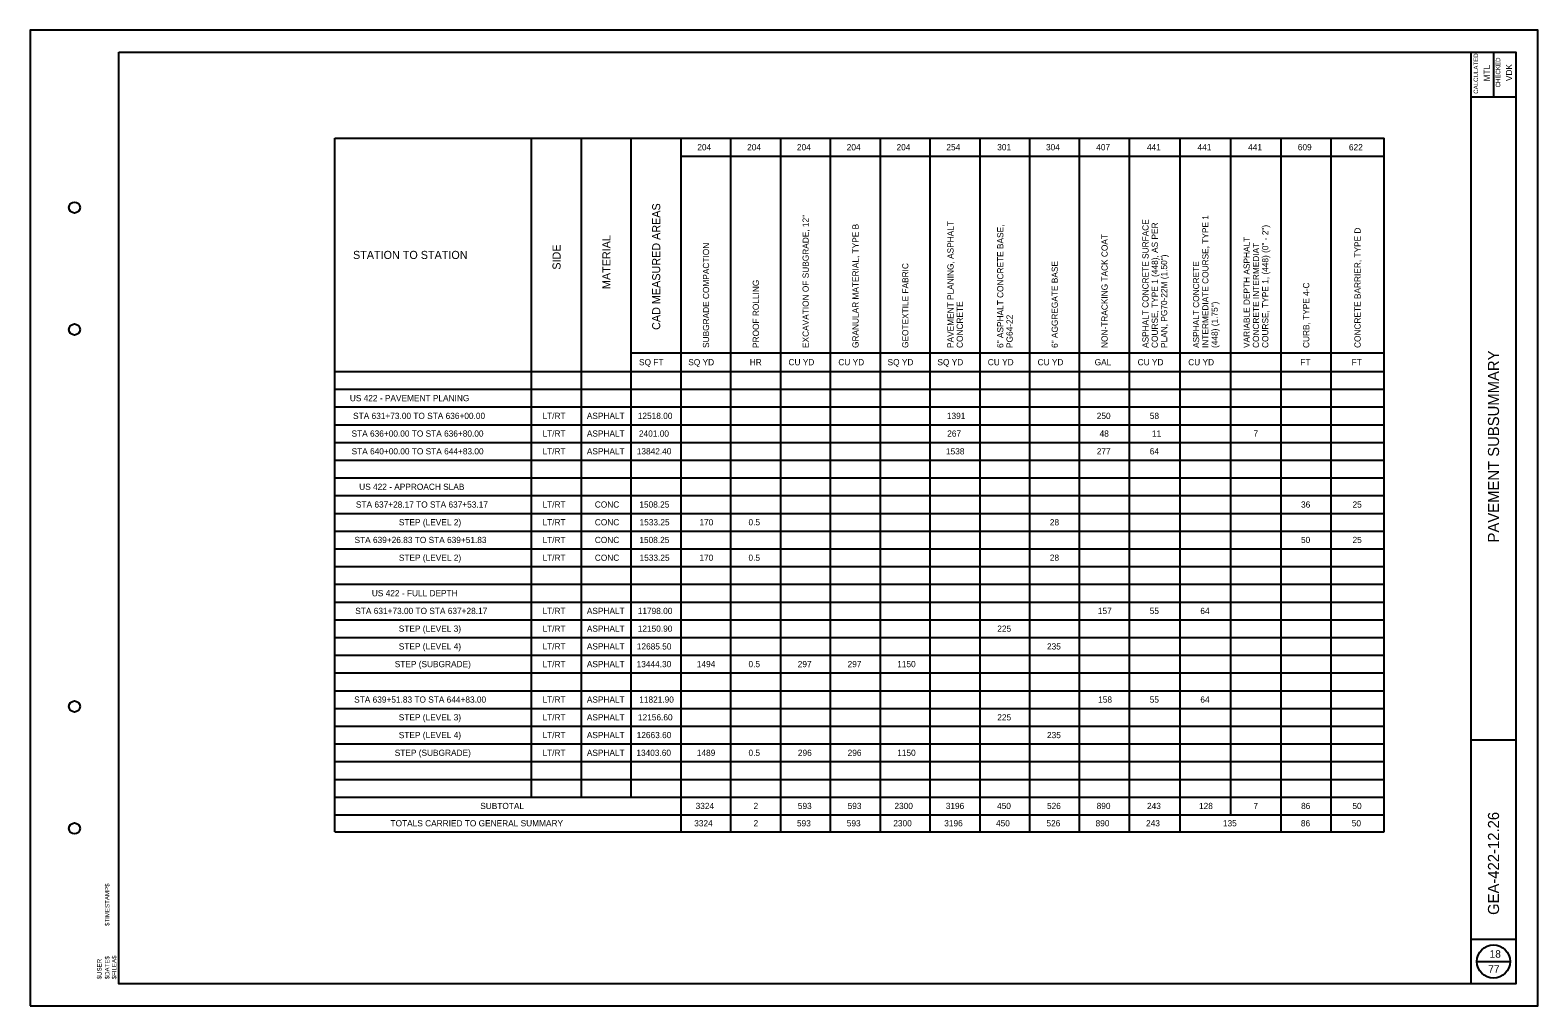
# Model space of a CAD drawing. Extents: x 0 to 34, y 0 to 22.
import ezdxf

# ---------------------------------------------------------------- set-up
doc = ezdxf.new("R2010")
doc.units = 0
for name, color, linetype in [('SH_Border', 7, 'Continuous'), ('SH_Cut_Line', 7, 'Continuous'), ('SH_Data', 7, 'Continuous'), ('SH_Text', 7, 'Continuous')]:
    doc.layers.add(name, color=color, linetype=linetype)

msp = doc.modelspace()

# ---------------------------------------------------------------- linework, layer by layer
at = {"layer": 'SH_Border'}
for p, q in [((32.5, 0.5), (32.5, 21.5)), ((33, 21.5), (33, 20.5)), ((32.5, 20.5), (33.5, 20.5)), ((32.5, 6), (33.5, 6)), ((32.5, 1.5), (33.5, 1.5))]:
    msp.add_line(p, q, dxfattribs=at)
msp.add_lwpolyline([(2, 21.5), (33.5, 21.5), (33.5, 0.5), (2, 0.5)], close=True, dxfattribs=at)
for centre in [(1, 18), (1, 15.25), (1, 6.75), (1, 4)]:
    msp.add_circle(centre, 0.125, dxfattribs=at)
at = {"layer": 'SH_Cut_Line'}
msp.add_lwpolyline([(0, 0), (34, 0), (34, 22), (0, 22)], close=True, dxfattribs=at)
at = {"layer": 'SH_Data'}
msp.add_line((32.625, 1), (33.375, 1), dxfattribs=at)
msp.add_circle((33, 1), 0.375, dxfattribs=at)
at = {"layer": 'SH_Text'}
for p, q in [((6.868, 19.561), (6.868, 19.561)), ((6.868, 19.561), (30.531, 19.561)), ((6.868, 3.927), (6.868, 19.561)), ((11.309, 4.707), (11.309, 19.561)), ((12.433, 4.707), (12.433, 19.561)), ((13.556, 4.707), (13.556, 19.561)), ((14.68, 3.927), (14.68, 19.561)), ((15.803, 3.927), (15.803, 19.561)), ((16.927, 3.927), (16.927, 19.561)), ((18.05, 3.927), (18.05, 19.561)), ((19.173, 3.927), (19.173, 19.561)), ((20.297, 3.927), (20.297, 19.561)), ((21.42, 3.927), (21.42, 19.561)), ((22.544, 3.927), (22.544, 19.561)), ((23.667, 3.927), (23.667, 19.561)), ((24.791, 3.927), (24.791, 19.561)), ((25.932, 3.927), (25.932, 19.561)), ((27.073, 4.307), (27.073, 19.561)), ((28.214, 3.927), (28.214, 19.561)), ((29.337, 3.927), (29.337, 19.561)), ((30.531, 3.927), (30.531, 19.561)), ((14.68, 19.161), (30.531, 19.161)), ((13.556, 14.723), (30.531, 14.723)), ((6.868, 14.303), (30.531, 14.303)), ((6.868, 13.903), (30.531, 13.903)), ((6.868, 13.503), (30.531, 13.503)), ((6.868, 13.103), (30.531, 13.103)), ((6.868, 12.704), (30.531, 12.704)), ((6.868, 12.304), (30.531, 12.304)), ((6.868, 11.904), (30.531, 11.904)), ((6.868, 11.504), (30.531, 11.504)), ((6.868, 11.104), (30.531, 11.104)), ((6.868, 10.704), (30.531, 10.704)), ((6.868, 10.305), (30.531, 10.305)), ((6.868, 9.905), (30.531, 9.905)), ((6.868, 9.505), (30.531, 9.505)), ((6.868, 9.105), (30.531, 9.105)), ((6.868, 8.705), (30.531, 8.705)), ((6.868, 8.305), (30.531, 8.305)), ((6.868, 7.906), (30.531, 7.906)), ((6.868, 7.506), (30.531, 7.506)), ((6.868, 7.106), (30.531, 7.106)), ((6.868, 6.706), (30.531, 6.706)), ((6.868, 6.306), (30.531, 6.306)), ((6.868, 5.906), (30.531, 5.906)), ((6.868, 5.507), (30.531, 5.507)), ((6.868, 5.107), (30.531, 5.107)), ((6.868, 4.707), (30.531, 4.707)), ((6.868, 4.307), (30.531, 4.307)), ((6.868, 3.927), (30.531, 3.927))]:
    msp.add_line(p, q, dxfattribs=at)

# ---------------------------------------------------------------- texts
at = {"layer": 'SH_Data'}
for s, height, rotation, p in [('CALCULATED', 0.1, 90, (32.652, 20.565)), ('MTL', 0.14, 90, (32.92, 20.844)), ('CHECKED', 0.1, 90, (33.152, 20.708)), ('VDK', 0.14, 90, (33.42, 20.851)), ('PAVEMENT SUBSUMMARY', 0.25, 90, (33.125, 10.449)), (' GEA-422-12.26 ', 0.25, 90, (33.125, 1.957)), ('$TIMESTAMP$', 0.1, 89.9931, (1.788, 1.8)), ('$USER', 0.1, 89.9931, (1.611, 0.598)), ('$DATE$', 0.1, 89.9931, (1.788, 0.598)), ('$FILEA$', 0.1, 89.9931, (1.944, 0.598))]:
    msp.add_text(s, height=height, rotation=rotation, dxfattribs=at).set_placement(p)
for s, p in [('18', (32.913, 1.085)), ('77', (32.882, 0.745))]:
    msp.add_text(s, height=0.17, dxfattribs=at).set_placement(p)
at = {"layer": 'SH_Text'}
for s, height, p in [('204', 0.14, (15.045, 19.291)), ('204', 0.14, (16.168, 19.291)), ('204', 0.14, (17.292, 19.291)), ('204', 0.14, (18.415, 19.291)), ('204', 0.14, (19.538, 19.291)), ('254', 0.14, (20.662, 19.291)), ('301', 0.14, (21.808, 19.291)), ('304', 0.14, (22.909, 19.291)), ('407', 0.14, (24.041, 19.291)), ('441', 0.14, (25.185, 19.291)), ('441', 0.14, (26.326, 19.291)), ('441', 0.14, (27.467, 19.291)), ('609', 0.14, (28.587, 19.291)), ('622', 0.14, (29.74, 19.291)), ('STATION TO STATION', 0.182, (7.281, 16.841)), ('SQ FT', 0.14, (13.731, 14.443)), ('SQ YD', 0.14, (14.842, 14.443)), ('HR', 0.14, (16.228, 14.443)), ('CU YD', 0.14, (17.102, 14.443)), ('CU YD', 0.14, (18.225, 14.443)), ('SQ YD', 0.14, (19.336, 14.443)), ('SQ YD', 0.14, (20.46, 14.443)), ('CU YD', 0.14, (21.596, 14.443)), ('CU YD', 0.14, (22.719, 14.443)), ('GAL', 0.14, (24.006, 14.443)), ('CU YD', 0.14, (24.975, 14.443)), ('CU YD', 0.14, (26.116, 14.443)), ('FT', 0.14, (28.644, 14.443)), ('FT', 0.14, (29.802, 14.443)), ('US 422 - PAVEMENT PLANING', 0.14, (7.209, 13.633)), ('STA 631+73.00 TO STA 636+00.00', 0.14, (7.283, 13.233)), ('LT/RT', 0.14, (11.554, 13.233)), ('ASPHALT', 0.14, (12.554, 13.233)), ('12518.00', 0.14, (13.703, 13.233)), ('1391', 0.14, (20.673, 13.233)), ('250', 0.14, (24.053, 13.233)), ('58', 0.14, (25.25, 13.233)), ('STA 636+00.00 TO STA 636+80.00', 0.14, (7.248, 12.834)), ('LT/RT', 0.14, (11.554, 12.834)), ('ASPHALT', 0.14, (12.554, 12.834)), ('2401.00', 0.14, (13.729, 12.834)), ('267', 0.14, (20.681, 12.834)), ('48', 0.14, (24.117, 12.834)), ('11', 0.14, (25.299, 12.834)), ('7', 0.14, (27.586, 12.834)), ('LT/RT', 0.14, (11.554, 12.434)), ('STA 640+00.00 TO STA 644+83.00', 0.14, (7.249, 12.434)), ('ASPHALT', 0.14, (12.554, 12.434)), ('13842.40', 0.14, (13.68, 12.434)), ('1538', 0.14, (20.653, 12.434)), ('277', 0.14, (24.053, 12.434)), ('64', 0.14, (25.248, 12.434)), ('US 422 - APPROACH SLAB', 0.14, (7.42, 11.634)), ('STA 637+28.17 TO STA 637+53.17', 0.14, (7.347, 11.234)), ('LT/RT', 0.14, (11.554, 11.234)), ('CONC', 0.14, (12.734, 11.234)), ('1508.25', 0.14, (13.738, 11.234)), ('36', 0.14, (28.66, 11.234)), ('25', 0.14, (29.821, 11.234)), ('STEP (LEVEL 2)', 0.14, (8.315, 10.834)), ('LT/RT', 0.14, (11.554, 10.834)), ('CONC', 0.14, (12.734, 10.834)), ('1533.25', 0.14, (13.743, 10.834)), ('170', 0.14, (15.093, 10.834)), ('0.5', 0.14, (16.199, 10.834)), ('28', 0.14, (22.995, 10.834)), ('STA 639+26.83 TO STA 639+51.83', 0.14, (7.315, 10.435)), ('LT/RT', 0.14, (11.554, 10.435)), ('CONC', 0.14, (12.734, 10.435)), ('1508.25', 0.14, (13.738, 10.435)), ('50', 0.14, (28.659, 10.435)), ('25', 0.14, (29.821, 10.435)), ('STEP (LEVEL 2)', 0.14, (8.315, 10.035)), ('LT/RT', 0.14, (11.554, 10.035)), ('CONC', 0.14, (12.734, 10.035)), ('1533.25', 0.14, (13.743, 10.035)), ('170', 0.14, (15.093, 10.035)), ('0.5', 0.14, (16.199, 10.035)), ('28', 0.14, (22.995, 10.035)), ('US 422 - FULL DEPTH', 0.14, (7.705, 9.235)), ('STA 631+73.00 TO STA 637+28.17', 0.14, (7.332, 8.835)), ('LT/RT', 0.14, (11.554, 8.835)), ('ASPHALT', 0.14, (12.554, 8.835)), ('11798.00', 0.14, (13.702, 8.835)), ('157', 0.14, (24.078, 8.835)), ('55', 0.14, (25.247, 8.835)), ('64', 0.14, (26.389, 8.835)), ('STEP (LEVEL 3)', 0.14, (8.313, 8.435)), ('LT/RT', 0.14, (11.554, 8.435)), ('ASPHALT', 0.14, (12.554, 8.435)), ('12150.90', 0.14, (13.702, 8.435)), ('225', 0.14, (21.81, 8.435)), ('STEP (LEVEL 4)', 0.14, (8.313, 8.035)), ('LT/RT', 0.14, (11.554, 8.035)), ('ASPHALT', 0.14, (12.554, 8.035)), ('12685.50', 0.14, (13.681, 8.035)), ('235', 0.14, (22.931, 8.035)), ('STEP (SUBGRADE)', 0.14, (8.222, 7.636)), ('LT/RT', 0.14, (11.554, 7.636)), ('ASPHALT', 0.14, (12.554, 7.636)), ('13444.30', 0.14, (13.677, 7.636)), ('1494', 0.14, (15.034, 7.636)), ('0.5', 0.14, (16.199, 7.636)), ('297', 0.14, (17.31, 7.636)), ('297', 0.14, (18.434, 7.636)), ('1150', 0.14, (19.553, 7.636)), ('STA 639+51.83 TO STA 644+83.00', 0.14, (7.307, 6.836)), ('LT/RT', 0.14, (11.554, 6.836)), ('ASPHALT', 0.14, (12.554, 6.836)), ('11821.90', 0.14, (13.736, 6.836)), ('158', 0.14, (24.085, 6.836)), ('55', 0.14, (25.247, 6.836)), ('64', 0.14, (26.389, 6.836)), ('STEP (LEVEL 3)', 0.14, (8.313, 6.436)), ('LT/RT', 0.14, (11.554, 6.436)), ('ASPHALT', 0.14, (12.554, 6.436)), ('12156.60', 0.14, (13.707, 6.436)), ('225', 0.14, (21.81, 6.436)), ('STEP (LEVEL 4)', 0.14, (8.313, 6.036)), ('LT/RT', 0.14, (11.554, 6.036)), ('ASPHALT', 0.14, (12.554, 6.036)), ('12663.60', 0.14, (13.678, 6.036)), ('235', 0.14, (22.931, 6.036)), ('STEP (SUBGRADE)', 0.14, (8.222, 5.636)), ('LT/RT', 0.14, (11.554, 5.636)), ('ASPHALT', 0.14, (12.554, 5.636)), ('13403.60', 0.14, (13.671, 5.636)), ('1489', 0.14, (15.034, 5.636)), ('0.5', 0.14, (16.199, 5.636)), ('296', 0.14, (17.313, 5.636)), ('296', 0.14, (18.436, 5.636)), ('1150', 0.14, (19.553, 5.636)), ('SUBTOTAL', 0.14, (10.15, 4.437)), ('3324', 0.14, (15.007, 4.437)), ('2', 0.14, (16.313, 4.437)), ('593', 0.14, (17.312, 4.437)), ('593', 0.14, (18.435, 4.437)), ('2300', 0.14, (19.491, 4.437)), ('3196', 0.14, (20.648, 4.437)), ('450', 0.14, (21.805, 4.437)), ('526', 0.14, (22.931, 4.437)), ('890', 0.14, (24.051, 4.437)), ('243', 0.14, (25.186, 4.437)), ('128', 0.14, (26.359, 4.437)), ('7', 0.14, (27.586, 4.437)), ('86', 0.14, (28.661, 4.437)), ('50', 0.14, (29.818, 4.437)), ('TOTALS CARRIED TO GENERAL SUMMARY', 0.14, (8.127, 4.047)), ('3324', 0.14, (14.975, 4.047)), ('2', 0.14, (16.313, 4.047)), ('593', 0.14, (17.292, 4.047)), ('593', 0.14, (18.416, 4.047)), ('2300', 0.14, (19.465, 4.047)), ('3196', 0.14, (20.613, 4.047)), ('450', 0.14, (21.781, 4.047)), ('526', 0.14, (22.919, 4.047)), ('890', 0.14, (24.027, 4.047)), ('243', 0.14, (25.165, 4.047)), ('135', 0.14, (26.898, 4.047)), ('86', 0.14, (28.657, 4.047)), ('50', 0.14, (29.804, 4.047))]:
    msp.add_text(s, height=height, dxfattribs=at).set_placement(p)
for s, height, p in [('CAD MEASURED AREAS', 0.182, (14.209, 15.242)), ('EXCAVATION OF SUBGRADE, 12"', 0.14, (17.558, 14.834)), ('PAVEMENT PLANING, ASPHALT', 0.14, (20.824, 14.834)), ('ASPHALT CONCRETE SURFACE', 0.14, (25.221, 14.834)), ('INTERMEDIATE COURSE, TYPE 1', 0.14, (26.572, 14.834)), ('MATERIAL', 0.182, (13.086, 16.162)), ('GRANULAR MATERIAL, TYPE B', 0.14, (18.682, 14.834)), ('6" ASPHALT CONCRETE BASE,', 0.14, (21.947, 14.834)), ('NON-TRACKING TACK COAT', 0.14, (24.299, 14.834)), ('COURSE, TYPE 1 (448), AS PER', 0.14, (25.431, 14.834)), ('COURSE, TYPE 1, (448) (0" - 2")', 0.14, (27.923, 14.834)), ('CONCRETE BARRIER, TYPE D', 0.14, (30.004, 14.834)), ('SIDE', 0.182, (11.962, 16.599)), ('SUBGRADE COMPACTION', 0.14, (15.311, 14.834)), ('VARIABLE DEPTH ASPHALT', 0.14, (27.503, 14.834)), ('CONCRETE INTERMEDIAT', 0.14, (27.713, 14.834)), ('GEOTEXTILE FABRIC', 0.14, (19.805, 14.834)), ('6" AGGREGATE BASE', 0.14, (23.175, 14.834)), ('PLAN, PG70-22M (1.50")', 0.14, (25.641, 14.834)), ('ASPHALT CONCRETE', 0.14, (26.362, 14.834)), ('PROOF ROLLING', 0.14, (16.435, 14.834)), ('CURB, TYPE 4-C', 0.14, (28.845, 14.834)), ('CONCRETE', 0.14, (21.034, 14.834)), ('(448) (1.75")', 0.14, (26.782, 14.834)), ('PG64-22', 0.14, (22.157, 14.834))]:
    msp.add_text(s, height=height, rotation=90, dxfattribs=at).set_placement(p)

doc.saveas('drawing.dxf')
